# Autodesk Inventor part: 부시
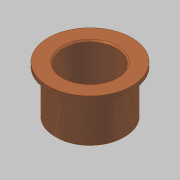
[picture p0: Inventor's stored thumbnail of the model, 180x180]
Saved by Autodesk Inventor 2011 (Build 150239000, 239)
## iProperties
Created: 2013-06
Part Number: 부시
Document SubType Name: Modeling
Designer: SeoGD™[esajin.kr]
Density: 1 g/cm^3
Mass: 31.4212 g
Surface Area: 129.264 cm^2
Volume: 31.4212 cm^3
Author: SeoGD™[esajin.kr]
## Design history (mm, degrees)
sketch "스케치1"
  geometry: C1 r 31 at (0, 0) reference; C2 r 25 at (0, 0) reference; C3 r 30 at (0, 0) reference; 1 further point
  node "참조1"
  node "참조2"
  node "참조4"
extrude "돌출1" new body sketch "스케치1" distance "d0" = 3; taper "d1" = 0 deg
extrude "돌출2" join sketch "스케치1" distance "d2" = 35; taper "d3" = 0 deg
chamfer "모따기1" distance "d6" = 1; stored, may be unused: second distance "d7" = 2, angle "d8" = 45 deg
sketch "스케치3"
  geometry: C1 r 19 at (0, 0); 1 further point
  constraints: 1 centre point, 1 coincident
  dimensions: "d13" = 38 diameter of C1
extrude "돌출4" cut sketch "스케치3" stored distance "d14" = 10; taper "d15" = 0 deg
chamfer "모따기3" distance "d16" = 1; stored, may be unused: second distance "d17" = 2, angle "d18" = 45 deg
node "솔리드1"
